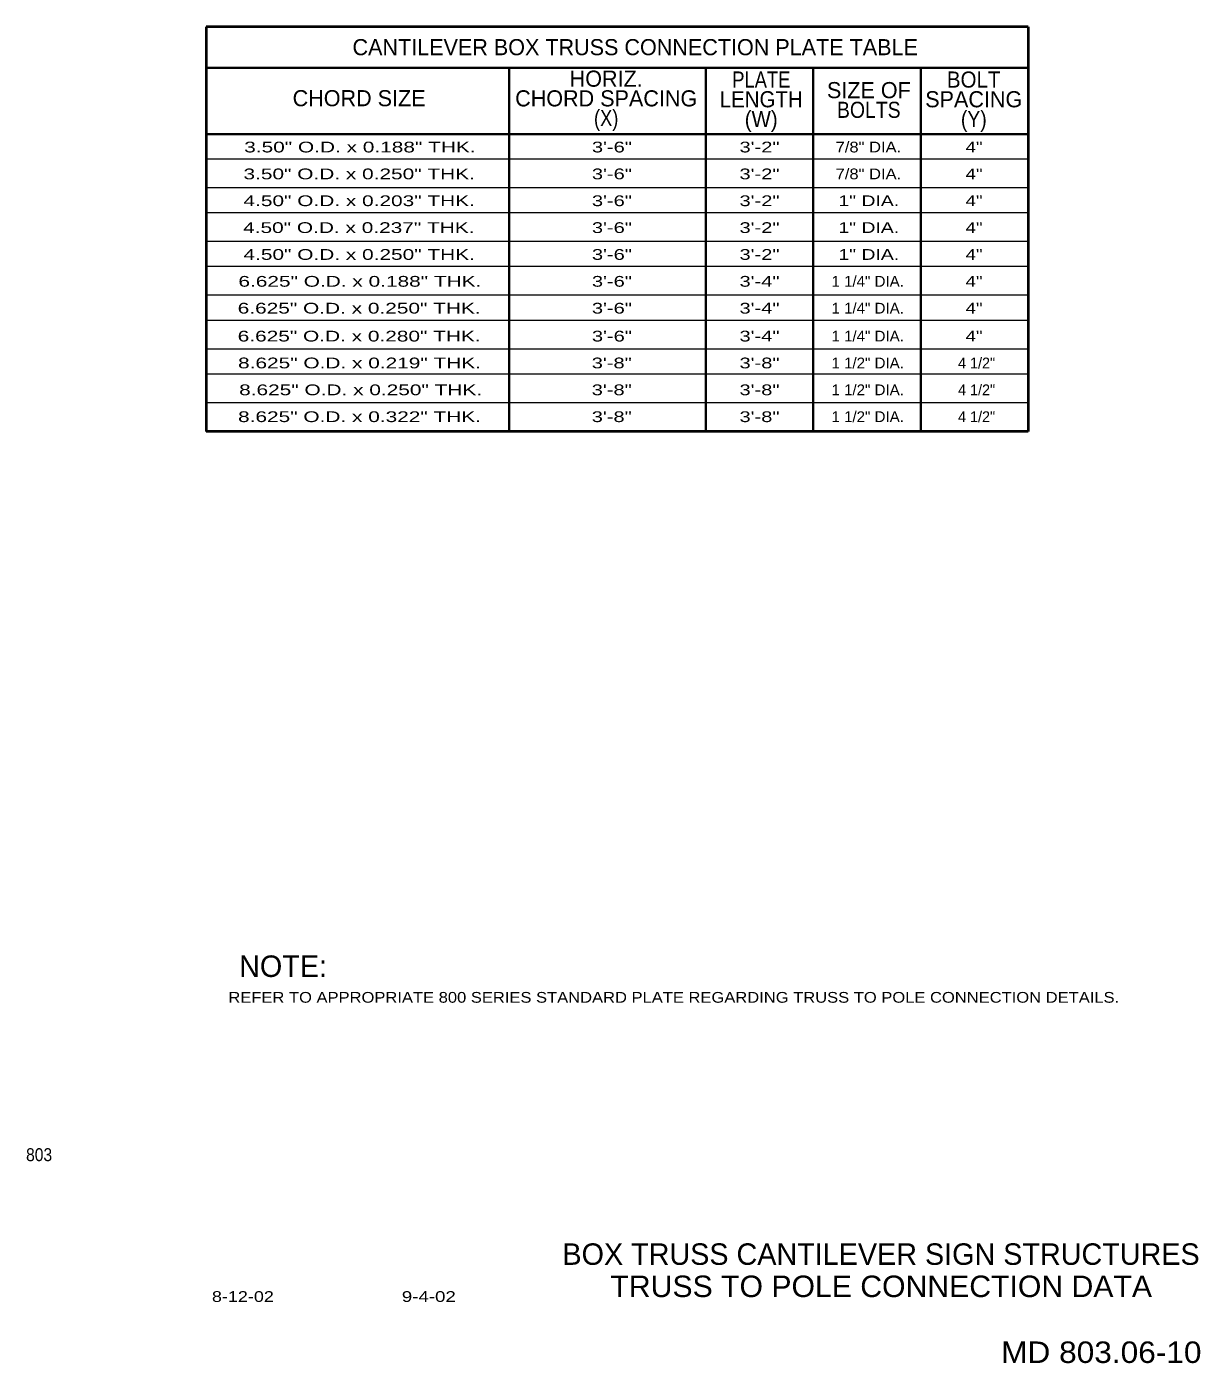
# Model space of a CAD drawing. Extents: x -34844.22 to -34837.67, y -181511.85 to -181504.39.
import ezdxf
from ezdxf.enums import TextEntityAlignment as Align

# ---------------------------------------------------------------- set-up
doc = ezdxf.new("R2010")
doc.units = 0
doc.header["$LTSCALE"] = 0.024
doc.layers.add('1', color=7, linetype='Continuous', lineweight=13)
doc.layers.add('12', color=7, linetype='Continuous')
doc.layers.add('13', color=7, linetype='Continuous')

msp = doc.modelspace()

# ---------------------------------------------------------------- linework, layer by layer
at = {"layer": '1', "lineweight": 40}
for p, q in [((-34838.627, -181504.388), (-34843.217, -181504.388)), ((-34843.217, -181504.388), (-34843.217, -181506.648)), ((-34838.627, -181504.388), (-34838.627, -181506.648)), ((-34838.627, -181506.648), (-34843.217, -181506.648))]:
    msp.add_line(p, q, dxfattribs=at)
at = {"layer": '1', "lineweight": 35}
for p, q in [((-34838.627, -181504.618), (-34843.217, -181504.618)), ((-34841.525, -181504.618), (-34841.525, -181506.648)), ((-34840.427, -181504.618), (-34840.427, -181506.648)), ((-34839.827, -181504.618), (-34839.827, -181506.648)), ((-34839.227, -181504.618), (-34839.227, -181506.648)), ((-34838.627, -181504.988), (-34843.217, -181504.988))]:
    msp.add_line(p, q, dxfattribs=at)
at = {"layer": '1'}
for p, q in [((-34838.627, -181505.128), (-34843.217, -181505.128)), ((-34838.627, -181505.288), (-34843.217, -181505.288)), ((-34838.627, -181505.428), (-34843.217, -181505.428)), ((-34838.627, -181505.588), (-34843.217, -181505.588)), ((-34838.627, -181505.728), (-34843.217, -181505.728)), ((-34838.627, -181505.888), (-34843.217, -181505.888)), ((-34838.627, -181506.028), (-34843.217, -181506.028)), ((-34838.627, -181506.188), (-34843.217, -181506.188)), ((-34838.627, -181506.328), (-34843.217, -181506.328)), ((-34838.627, -181506.488), (-34843.217, -181506.488))]:
    msp.add_line(p, q, dxfattribs=at)

# ---------------------------------------------------------------- texts
at = {"layer": '12'}
for s, height, p in [('CANTILEVER BOX TRUSS CONNECTION PLATE TABLE', 0.09, (-34840.821, -181504.547)), ('HORIZ.', 0.09, (-34840.983, -181504.723)), ('SIZE OF', 0.09, (-34839.5165, -181504.787)), ('CHORD SIZE', 0.09, (-34842.3625, -181504.832)), ('CHORD SPACING', 0.09, (-34840.983, -181504.833)), ('SPACING', 0.09, (-34838.931, -181504.838)), ('NOTE:', 0.12, (-34842.787, -181509.695))]:
    msp.add_text(s, height=height, dxfattribs=at).set_placement(p, align=Align.CENTER)
for s, width, p in [('PLATE', 0.85, (-34840.117, -181504.728)), ('BOLT', 0.95, (-34838.9315, -181504.728)), ('LENGTH', 0.95, (-34840.1175, -181504.838)), ('(X)', 0.85, (-34840.983, -181504.943)), ('(W)', 0.95, (-34840.1175, -181504.948)), ('BOLTS', 0.9, (-34839.517, -181504.897)), ('(Y)', 0.9, (-34838.9305, -181504.948))]:
    msp.add_text(s, height=0.09, dxfattribs=dict(at, width=width)).set_placement(p, align=Align.CENTER)
at = {"layer": '13'}
for s, height, width, p in [('3.50" O.D. x 0.188" THK.', 0.06, 1.45, (-34842.358, -181505.09)), ('3\'-6"', 0.06, 1.4, (-34840.951, -181505.09)), ('3\'-2"', 0.06, 1.4, (-34840.127, -181505.09)), ('7/8" DIA.', 0.06, 1.15, (-34839.519, -181505.09)), ('4"', 0.06, 1.3, (-34838.929, -181505.09)), ('3.50" O.D. x 0.250" THK.', 0.06, 1.45, (-34842.362, -181505.24)), ('3\'-6"', 0.06, 1.4, (-34840.951, -181505.24)), ('3\'-2"', 0.06, 1.4, (-34840.127, -181505.24)), ('7/8" DIA.', 0.06, 1.15, (-34839.519, -181505.24)), ('4"', 0.06, 1.3, (-34838.929, -181505.24)), ('4.50" O.D. x 0.203" THK.', 0.06, 1.45, (-34842.362, -181505.39)), ('3\'-6"', 0.06, 1.4, (-34840.951, -181505.39)), ('3\'-2"', 0.06, 1.4, (-34840.127, -181505.39)), ('1" DIA.', 0.06, 1.35, (-34839.517, -181505.39)), ('4"', 0.06, 1.3, (-34838.929, -181505.39)), ('4.50" O.D. x 0.237" THK.', 0.06, 1.45, (-34842.364, -181505.54)), ('3\'-6"', 0.06, 1.4, (-34840.951, -181505.54)), ('3\'-2"', 0.06, 1.4, (-34840.127, -181505.54)), ('1" DIA.', 0.06, 1.35, (-34839.517, -181505.54)), ('4"', 0.06, 1.3, (-34838.929, -181505.54)), ('4.50" O.D. x 0.250" THK.', 0.06, 1.45, (-34842.362, -181505.69)), ('3\'-6"', 0.06, 1.4, (-34840.951, -181505.69)), ('3\'-2"', 0.06, 1.4, (-34840.127, -181505.69)), ('1" DIA.', 0.06, 1.35, (-34839.517, -181505.69)), ('4"', 0.06, 1.3, (-34838.929, -181505.69)), ('6.625" O.D. x 0.188" THK.', 0.06, 1.45, (-34842.358, -181505.84)), ('3\'-6"', 0.06, 1.4, (-34840.951, -181505.84)), ('3\'-4"', 0.06, 1.4, (-34840.127, -181505.84)), ('1 1/4" DIA.', 0.06, 1.05, (-34839.523, -181505.84)), ('4"', 0.06, 1.3, (-34838.929, -181505.84)), ('6.625" O.D. x 0.250" THK.', 0.06, 1.45, (-34842.362, -181505.99)), ('3\'-6"', 0.06, 1.4, (-34840.951, -181505.99)), ('3\'-4"', 0.06, 1.4, (-34840.127, -181505.99)), ('1 1/4" DIA.', 0.06, 1.05, (-34839.523, -181505.99)), ('4"', 0.06, 1.3, (-34838.929, -181505.99)), ('6.625" O.D. x 0.280" THK.', 0.06, 1.45, (-34842.362, -181506.146)), ('3\'-6"', 0.06, 1.4, (-34840.951, -181506.146)), ('3\'-4"', 0.06, 1.4, (-34840.127, -181506.146)), ('1 1/4" DIA.', 0.06, 1.05, (-34839.523, -181506.146)), ('4"', 0.06, 1.3, (-34838.929, -181506.146)), ('8.625" O.D. x 0.219" THK.', 0.06, 1.45, (-34842.36, -181506.296)), ('3\'-8"', 0.06, 1.4, (-34840.952, -181506.296)), ('3\'-8"', 0.06, 1.4, (-34840.127, -181506.296)), ('1 1/2" DIA.', 0.06, 1.05, (-34839.523, -181506.296)), ('8.625" O.D. x 0.250" THK.', 0.06, 1.45, (-34842.354, -181506.446)), ('3\'-8"', 0.06, 1.4, (-34840.952, -181506.446)), ('3\'-8"', 0.06, 1.4, (-34840.127, -181506.446)), ('1 1/2" DIA.', 0.06, 1.05, (-34839.523, -181506.446)), ('8.625" O.D. x 0.322" THK.', 0.06, 1.45, (-34842.36, -181506.596)), ('3\'-8"', 0.06, 1.4, (-34840.952, -181506.596)), ('3\'-8"', 0.06, 1.4, (-34840.127, -181506.596)), ('1 1/2" DIA.', 0.06, 1.05, (-34839.523, -181506.596)), ('803', 0.07251, 0.9, (-34844.149, -181510.724)), ('TRUSS TO POLE CONNECTION DATA', 0.12, 1.05, (-34839.4475, -181511.483))]:
    msp.add_text(s, height=height, dxfattribs=dict(at, width=width)).set_placement(p, align=Align.CENTER)
for s, height, p in [('4 1/2"', 0.06, (-34838.915, -181506.296)), ('4 1/2"', 0.06, (-34838.915, -181506.446)), ('4 1/2"', 0.06, (-34838.915, -181506.596)), ('BOX TRUSS CANTILEVER SIGN STRUCTURES', 0.12, (-34839.4485, -181511.303))]:
    msp.add_text(s, height=height, dxfattribs=at).set_placement(p, align=Align.CENTER)
at = {"layer": '13', "width": 1.15}
msp.add_text('REFER TO APPROPRIATE 800 SERIES STANDARD PLATE REGARDING TRUSS TO POLE CONNECTION DETAILS.', height=0.06, dxfattribs=at).set_placement((-34838.119, -181509.839), align=Align.RIGHT)
at = {"layer": '13'}
for s, height, width, p in [('8-12-02', 0.06, 1.25, (-34843.184, -181511.51)), ('9-4-02', 0.06, 1.3, (-34842.124, -181511.51)), ('MD 803.06-10', 0.12, 1.1, (-34838.778, -181511.851))]:
    msp.add_text(s, height=height, dxfattribs=dict(at, width=width)).set_placement(p)

doc.saveas('drawing.dxf')
